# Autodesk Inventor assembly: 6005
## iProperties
Shininess: 64.0
Length Units: 11269
Angle Units: 11279
Time Units: 11290
Mass Units: 11283
Length Display Precision: 3
Angle Display Precision: 2
Compacted: True
Created: 2004-09
Part Number: 6005
Document SubType Name: Assembly
Density: 0.0
Volumn: 0.0
Area: 0.0
PropertySet Name: Model Information
Control State: 0
Master: False
Checked Out: False
